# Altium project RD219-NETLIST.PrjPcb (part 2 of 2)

## Sheet 7.SchDoc
size 420 x 297 mm
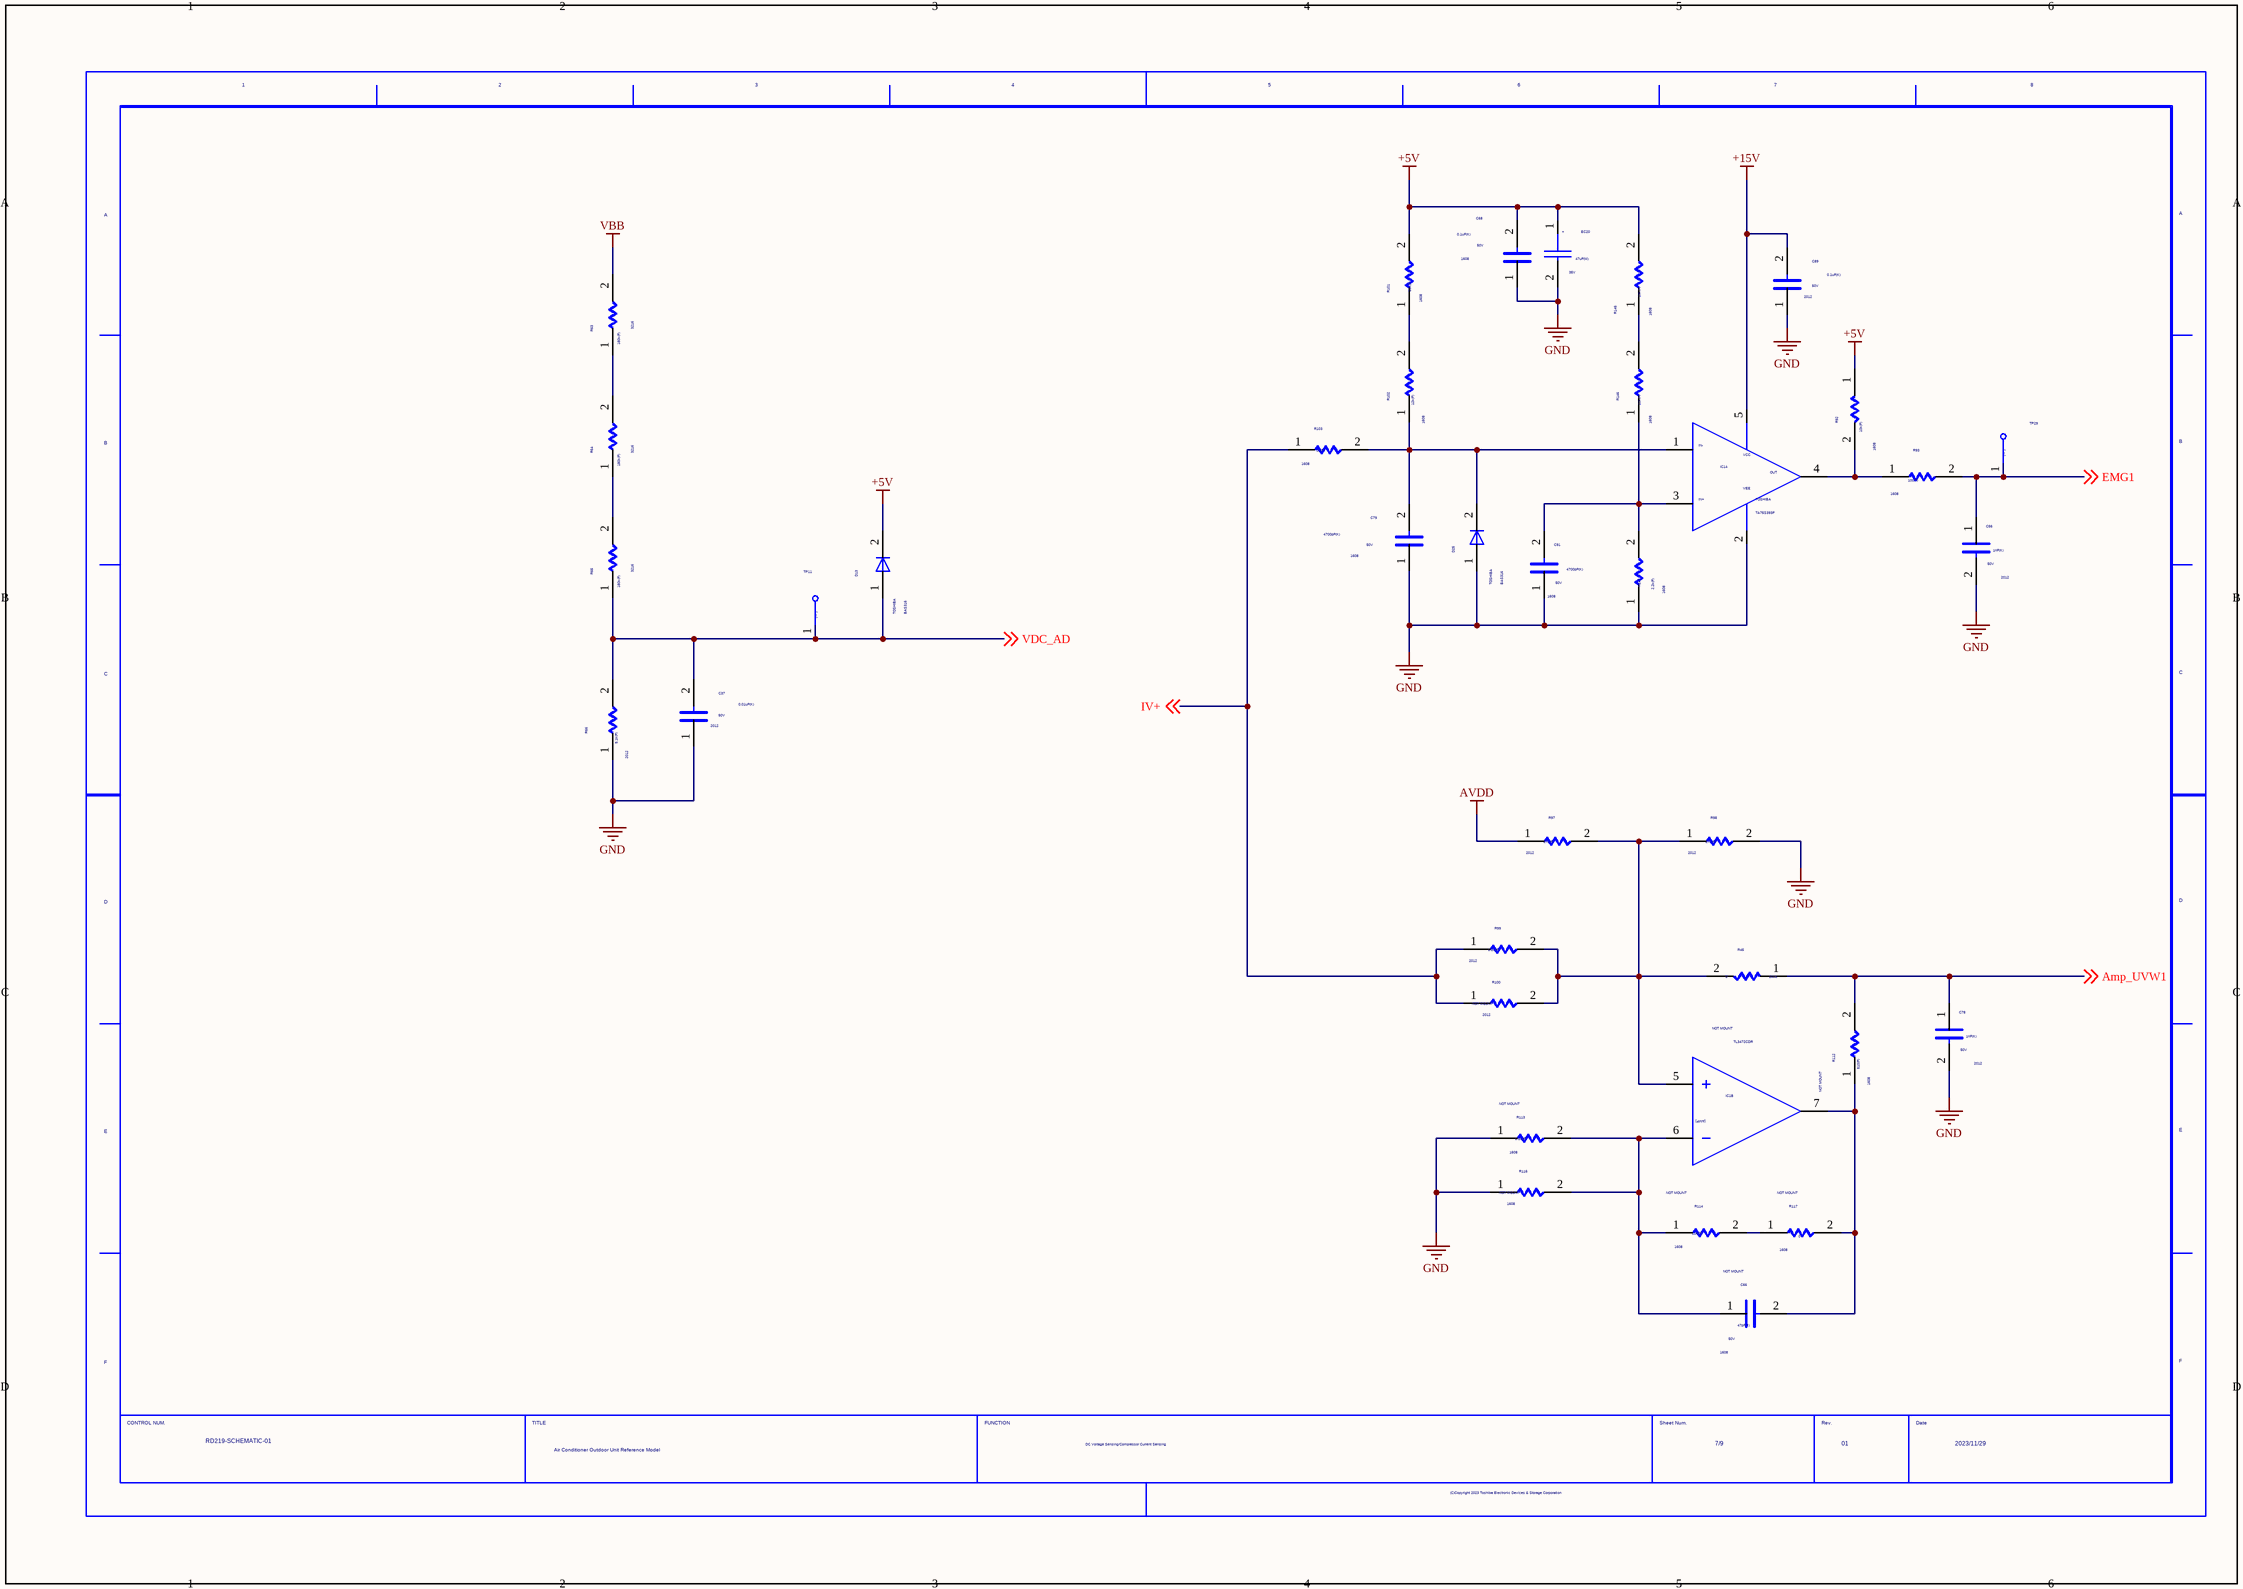
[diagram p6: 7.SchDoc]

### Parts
(Parts that share a designator on the sheet are numbered #1, #2 ... from top to bottom, then left to right.)
C37  SIZECODESMD: 2012  VAL2: 50V  VAL1: 0.01uF(K)  (hidden comment: C)
C56  VAL2: 50V  SIZECODESMD: 2012  VAL1: 1nF(K)  (hidden comment: C)
C66  NOTMOUNT: NOT MOUNT  VAL2: 50V  SIZECODESMD: 1608  VAL1: 47pF(J)  (hidden comment: C)
C68  VAL2: 50V  SIZECODESMD: 1608  VAL1: 0.1uF(K)  (hidden comment: C)
C78  VAL2: 50V  SIZECODESMD: 2012  VAL1: 1nF(K)  (hidden comment: C)
C79  VAL2: 50V  SIZECODESMD: 1608  VAL1: 4700pF(K)  (hidden comment: C)
C89  VAL2: 50V  SIZECODESMD: 2012  VAL1: 0.1uF(K)  (hidden comment: C)
C91  VAL2: 50V  SIZECODESMD: 1608  VAL1: 4700pF(K)  (hidden comment: C)
D13  USERCOMPTEXT3: TOSHIBA  VAL3: BAS316  (hidden comment: D_CUSTOM)
D25  USERCOMPTEXT3: TOSHIBA  VAL3: BAS316  (hidden comment: D_CUSTOM)
EC20  VAL2: 35V  VAL1: 47uF(M)  (hidden comment: EC)
IC1  NOTMOUNT: NOT MOUNT  VAL3: TL3472CDR  (hidden comment: AMP_1)  (part B of 2)
IC14  USERCOMPTEXT3: TOSHIBA  (hidden comment: TA75S393F)
R45  SIZECODESMD: 1608  VAL1: 0  (hidden comment: R)
R63  SIZECODESMD: 3216  VAL1: 180k(F)  (hidden comment: R)
R64  SIZECODESMD: 3216  VAL1: 180k(F)  (hidden comment: R)
R65  SIZECODESMD: 3216  VAL1: 180k(F)  (hidden comment: R)
R66  VAL1: 5.1k(F)  SIZECODESMD: 2012  (hidden comment: R)
R92  SIZECODESMD: 1608  VAL1: 10k(F)  (hidden comment: R)
R93  SIZECODESMD: 1608  VAL1: 100(F)  (hidden comment: R)
R97  SIZECODESMD: 2012  VAL1: 27k(F)  (hidden comment: R)
R98  SIZECODESMD: 2012  VAL1: 27k(F)  (hidden comment: R)
R99  SIZECODESMD: 2012  VAL1: 1.2k(F)  (hidden comment: R)
R100  SIZECODESMD: 2012  NOTMOUNT: NOT MOUNT  (hidden comment: R)
R101  SIZECODESMD: 1608  VAL1: 20k(F)  (hidden comment: R)
R102  SIZECODESMD: 1608  VAL1: 12k(F)  (hidden comment: R)
R103  SIZECODESMD: 1608  VAL1: 2k(F)  (hidden comment: R)
R112  NOTMOUNT: NOT MOUNT  SIZECODESMD: 1608  VAL1: 510(F)  (hidden comment: R)
R113  NOTMOUNT: NOT MOUNT  SIZECODESMD: 1608  VAL1: 1.1k(F)  (hidden comment: R)
R114  NOTMOUNT: NOT MOUNT  SIZECODESMD: 1608  VAL1: 12k(F)  (hidden comment: R)
R116  SIZECODESMD: 1608  NOTMOUNT: NOT MOUNT  (hidden comment: R)
R117  NOTMOUNT: NOT MOUNT  SIZECODESMD: 1608  VAL1: 0  (hidden comment: R)
R145  SIZECODESMD: 1608  VAL1: 10k(F)  (hidden comment: R)
R146  SIZECODESMD: 1608  VAL1: 12k(F)  (hidden comment: R)
R147  SIZECODESMD: 1608  VAL1: 2.2k(F)  (hidden comment: R)
TP11  TP  (value not drawn)
TP29  TP  (value not drawn)
U?#7  DATE: 2023/11/29  TITLE: Air Conditioner Outdoor Unit / Reference Model  FUNCTION: DC Voltage Sensing/Compressor Current Sensing  DRAWINGNUMBER: RD219-SCHEMATIC-01  SHEETNUMBER: 7/9  REVISION: 01  (hidden comment: WAKU_DEF100)

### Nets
+5V: C68.2 D13.2 EC20.1 R92.1 R101.2 R145.2
+15V: C89.2 IC14.5
AVDD: R97.1
GND: C37.1 C56.2 C68.1 C78.2 C79.1 C89.1 C91.1 D25.1 EC20.2 IC14.2 R66.1 R98.2 R113.1 R116.1 R147.1
VBB: R63.2
Amp_UVW1: C78.1 R45.1 R112.2 ; off-sheet Amp_UVW1
EMG1: C56.1 R93.2 TP29.1 ; off-sheet EMG1
IV+: R99.1 R100.1 R103.1 ; off-sheet IV+
NetC66_1: C66.1 IC1.6 R113.2 R114.1 R116.2
NetC66_2: C66.2 IC1.7 R112.1 R117.2
NetC79_2: C79.2 D25.2 IC14.1 R102.1 R103.2
NetC91_2: C91.2 IC14.3 R146.1 R147.2
NetIC1_5: IC1.5 R45.2 R97.2 R98.1 R99.2 R100.2
NetIC14_4: IC14.4 R92.2 R93.1
NetR63_1: R63.1 R64.2
NetR64_1: R64.1 R65.2
NetR101_1: R101.1 R102.2
NetR114_2: R114.2 R117.1
NetR145_1: R145.1 R146.2
VDC_AD: C37.2 D13.1 R65.1 R66.2 TP11.1 ; off-sheet VDC_AD

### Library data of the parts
C37 = C: OriginalSymbolOrigin: (2540,7620); VAL3: AC0805KRX7R9BB103
C56 C78 = C: OriginalSymbolOrigin: (2540,7620); COMP: AC0805KRX7R9BB102
C66 = C: OriginalSymbolOrigin: (2540,7620); COMP: AC0603JRNPO9BN470
C68 C89 = C: OriginalSymbolOrigin: (2540,7620); COMP: AC0603KRX7R9BB104
C79 C91 = C: OriginalSymbolOrigin: (2540,7620); COMP: AC0603KRX7R9BB472
D13 D25 = D_CUSTOM: SAVEAREA0: -1668,-97,14265,7829; SAVECOUNT: 4; TIME: 14:49:55; UPDATEUSER: w20165dm; UPDATETIME: 16:47:49; OriginalSymbolOrigin: (5080,5080)
EC20 = EC: SAVEAREA0: -1432,-1528,20311,14389; SAVECOUNT: 53; TIME: 15:02:55; UPDATEUSER: w20165dm; UPDATETIME: 16:35:05; OriginalSymbolOrigin: (2540,10160); VAL3: CS1V470M_CRE54
IC1 = AMP_1: SAVEAREA0: -6226,-235,36343,20943; TIME: 17:09:52; UPDATEUSER: w20165dm; SAVECOUNT: 1; OriginalSymbolOrigin: (5080,20320); CaptureCellPackProp: AMP_1B; FUNCN: IC1_2
IC14 = TA75S393F: SAVECOUNT: 22; SAVEAREA0: -11585,-294,41625,26178; TIME: 20:02:00; UPDATEUSER: w20165dm; UPDATETIME: 20:02:39; OriginalSymbolOrigin: (5080,22860)
R45 = R: OriginalSymbolOrigin: (5080,5080); COMP: AC0603FR_070RL; VAL3: AC0603FR-070RL; VAL2: 100mW
R63-R65 = R: OriginalSymbolOrigin: (5080,5080); VAL3: AC1206FR-07180KL; VAL2: 250mW; COMP: AC1206FR_07180KL
R66 = R: OriginalSymbolOrigin: (5080,5080); VAL3: AC0805FR-075K1L; VAL2: 125mW; COMP: AC0805FR_075K1L
R92 = R_Dup1: OriginalSymbolOrigin: (5080,5080); VAL2: 100mW; VAL3: AC0603FR_0710KL
R93 = R: OriginalSymbolOrigin: (5080,5080); COMP: AC0603FR_07100RL; VAL2: 100mW
R97 R98 = R: OriginalSymbolOrigin: (5080,5080); COMP: AC0805FR_0727KL; VAL2: 125mW
R99 = R: OriginalSymbolOrigin: (5080,5080); COMP: AC0805FR_071K2L; VAL2: 125mW
R100 = R: OriginalSymbolOrigin: (5080,5080); COMP: SMT_0805_R; VAL3: NC
R101 = R_Dup1: OriginalSymbolOrigin: (5080,5080); VAL3: AC0603FR_0720KL; VAL2: 100mW
R102 R146 = R_Dup1: OriginalSymbolOrigin: (5080,5080); VAL3: AC0603FR_0712KL; VAL2: 100mW
R103 = R: OriginalSymbolOrigin: (5080,5080); COMP: AC0603FR_072KL; VAL2: 100mW
R112 = R_Dup1: OriginalSymbolOrigin: (5080,5080); VAL2: 100mW; VAL3: AC0603FR_07510RL
R113 = R: OriginalSymbolOrigin: (5080,5080); COMP: AC0603FR_071K1L; VAL2: 100mW
R114 = R: OriginalSymbolOrigin: (5080,5080); COMP: AC0603FR_0712KL; VAL2: 100mW
R116 = R: OriginalSymbolOrigin: (5080,5080); COMP: SMT_0603_R
R117 = R: OriginalSymbolOrigin: (5080,5080); COMP: AC0603FR_070RL; VAL2: 100mW
R145 = R_Dup1: OriginalSymbolOrigin: (5080,5080); VAL3: AC0603FR_0710KL; VAL2: 100mW
R147 = R_Dup1: OriginalSymbolOrigin: (5080,5080); VAL3: AC0603FR_072K2L; VAL2: 100mW
TP11 = TP_Dup1: TIME: 16:12:21; UPDATEUSER: fukuda-y; UPDATETIME: 16:18:11; SAVECOUNT: 2; SAVEAREA0: -242,-92,12810,7836; OriginalSymbolOrigin: (0,7620); COMPCOMMENT: VDC_AD; VAL3: ZXD
TP29 = TP_Dup1: TIME: 16:12:21; UPDATEUSER: fukuda-y; UPDATETIME: 16:18:11; SAVECOUNT: 2; SAVEAREA0: -242,-92,12810,7836; OriginalSymbolOrigin: (0,7620); COMPCOMMENT: EMG1; VAL3: ZXD
U?#7 = WAKU_DEF100: PLOTTIME: HH:MM; SAVEAREA0: -45080,-4508,463680,304612; TIME: 18:03:30; UPDATEUSER: sptcae13; UPDATETIME: 08:19:31; SAVECOUNT: 8; OriginalSymbolOrigin: (10160,284480)

## Sheet 8.SchDoc
size 420 x 297 mm
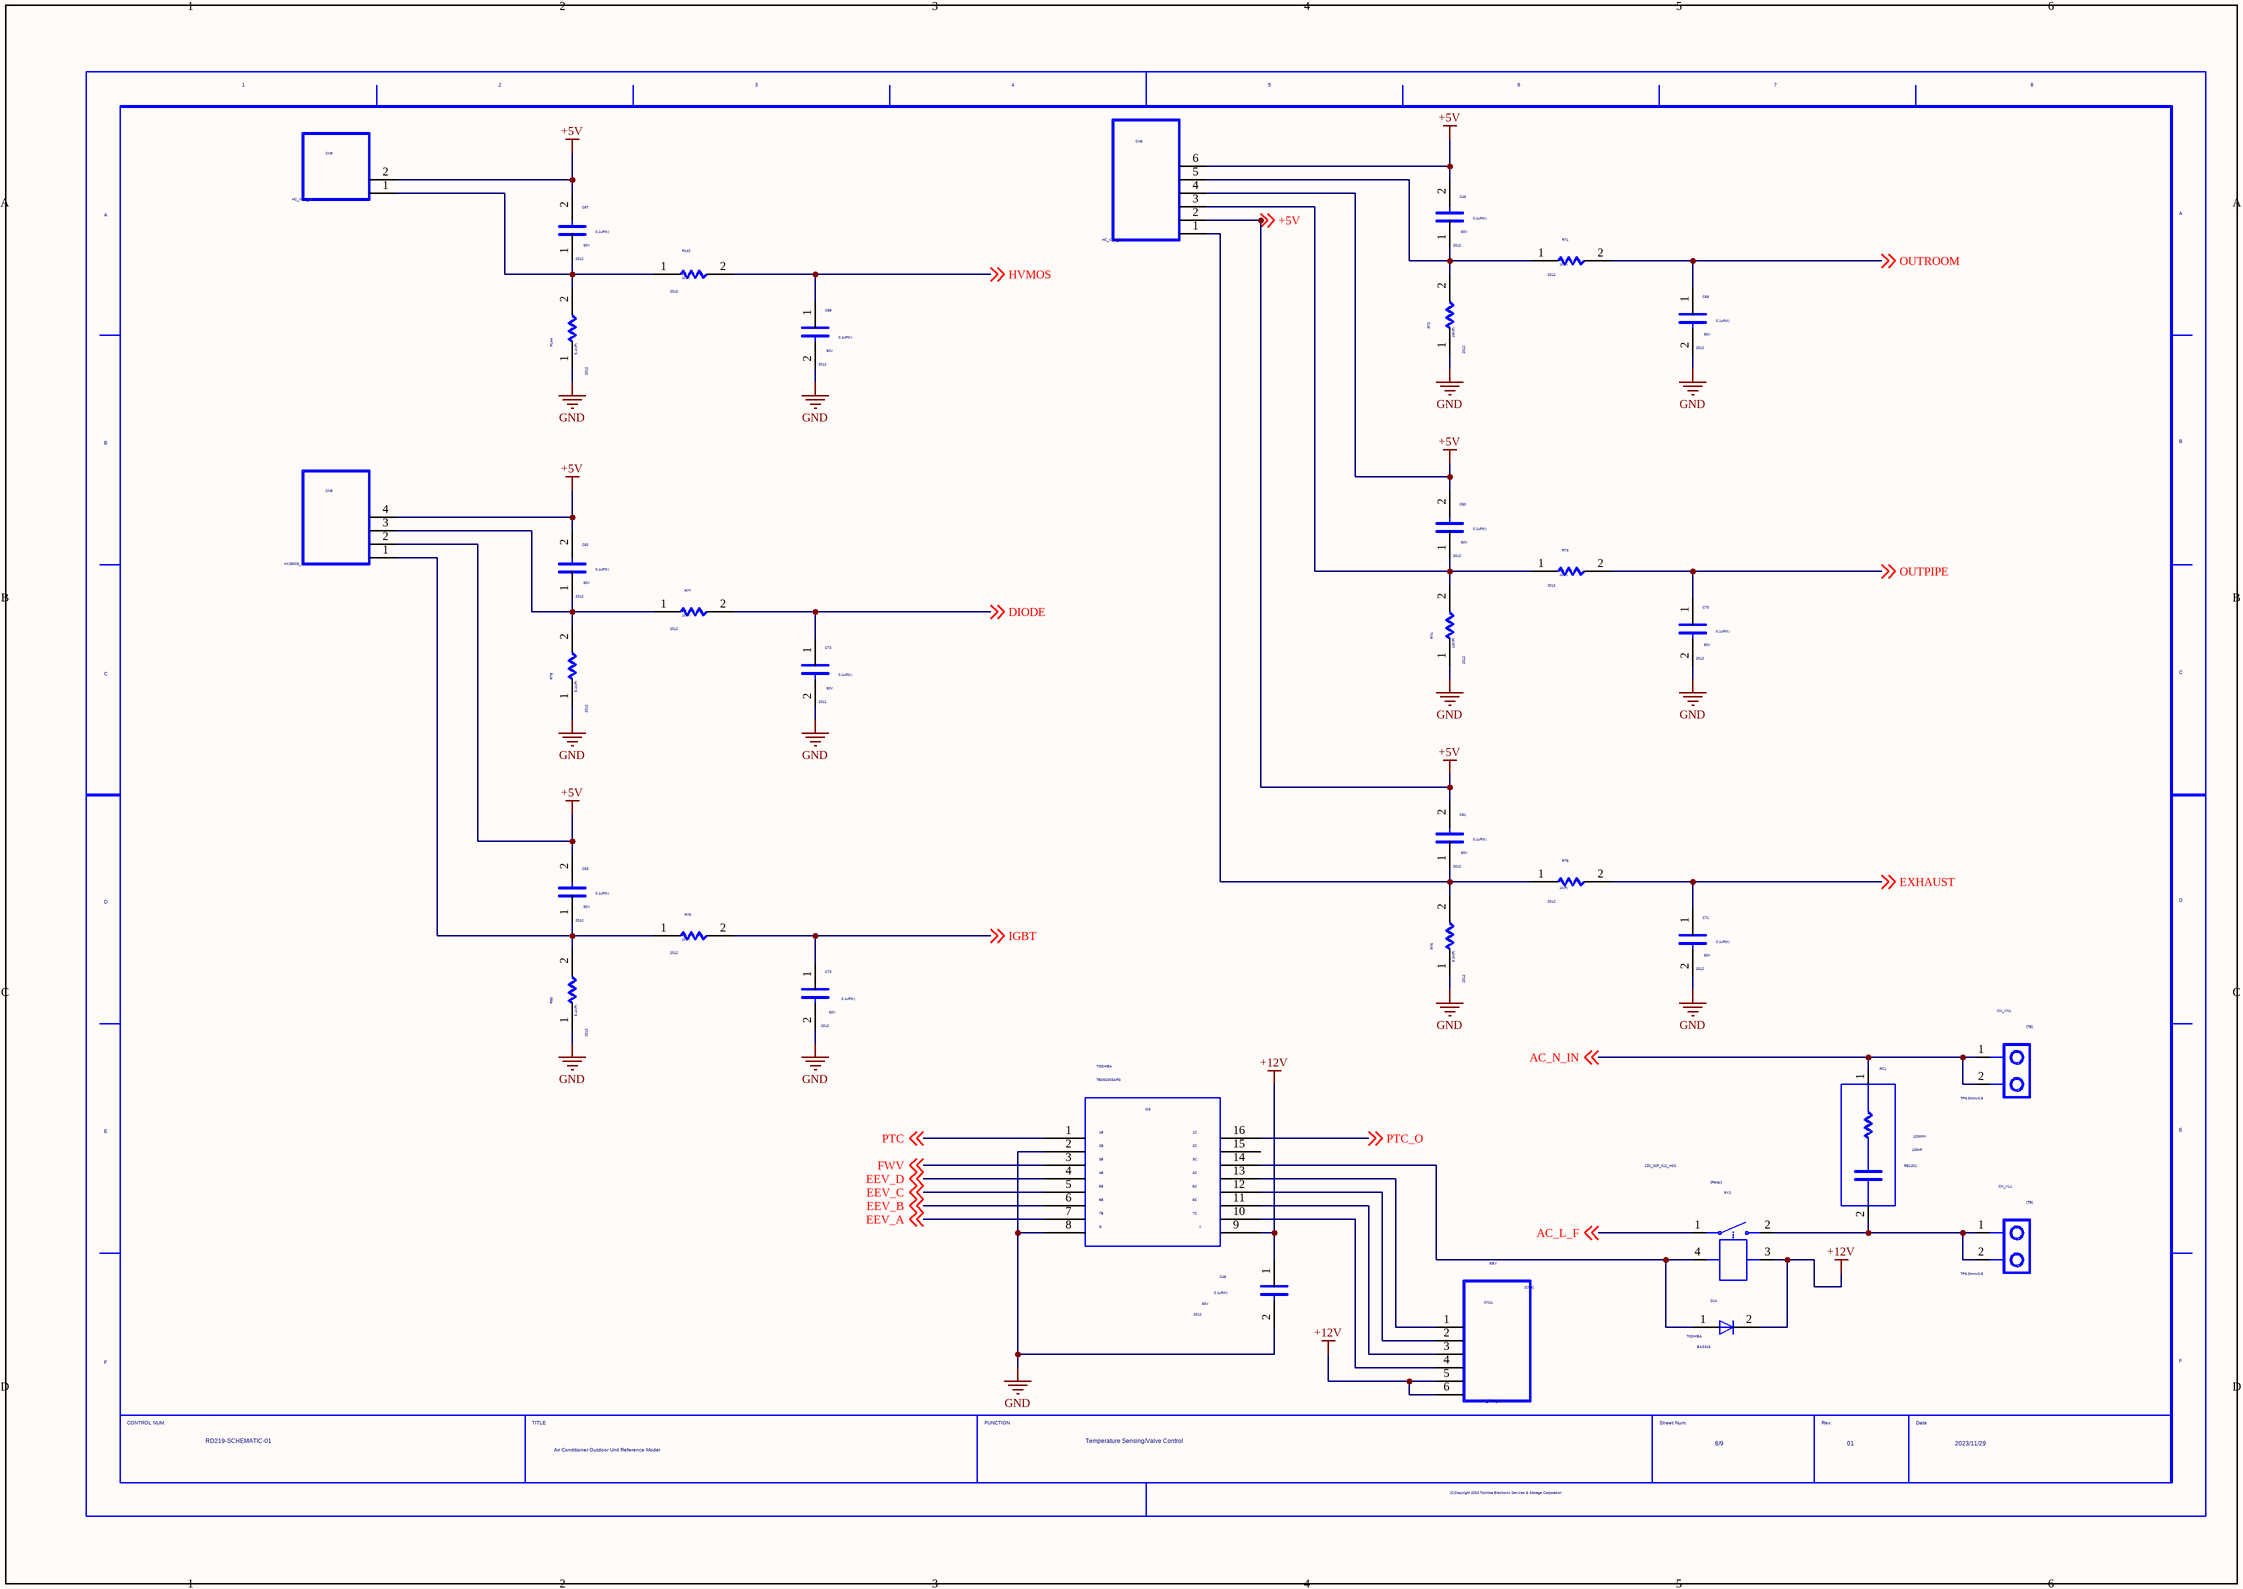
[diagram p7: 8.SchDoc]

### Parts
(Parts that share a designator on the sheet are numbered #1, #2 ... from top to bottom, then left to right.)
C48  SIZECODESMD: 2012  VAL2: 50V  VAL1: 0.1uF(K)  (hidden comment: C)
C49  SIZECODESMD: 2012  VAL2: 50V  VAL1: 0.1uF(K)  (hidden comment: C)
C50  SIZECODESMD: 2012  VAL2: 50V  VAL1: 0.1uF(K)  (hidden comment: C)
C51  SIZECODESMD: 2012  VAL2: 50V  VAL1: 0.1uF(K)  (hidden comment: C)
C52  SIZECODESMD: 2012  VAL2: 50V  VAL1: 0.1uF(K)  (hidden comment: C)
C53  SIZECODESMD: 2012  VAL2: 50V  VAL1: 0.1uF(K)  (hidden comment: C)
C69  SIZECODESMD: 2012  VAL2: 50V  VAL1: 0.1uF(K)  (hidden comment: C)
C70  SIZECODESMD: 2012  VAL2: 50V  VAL1: 0.1uF(K)  (hidden comment: C)
C71  SIZECODESMD: 2012  VAL2: 50V  VAL1: 0.1uF(K)  (hidden comment: C)
C72  SIZECODESMD: 2012  VAL2: 50V  VAL1: 0.1uF(K)  (hidden comment: C)
C73  SIZECODESMD: 2012  VAL2: 50V  VAL1: 0.1uF(K)  (hidden comment: C)
C87  SIZECODESMD: 2012  VAL2: 50V  VAL1: 0.1uF(K)  (hidden comment: C)
C88  SIZECODESMD: 2012  VAL2: 50V  VAL1: 0.1uF(K)  (hidden comment: C)
CN5  VAL3: HC_XHB_6A  (hidden comment: CN6Y)
CN8  VAL3: HX25003_4A  (hidden comment: CN4Y)
CN9  VAL3: HC_XHB_2A  (hidden comment: CN2Y)
CN11  VAL3: HC_XHB_6A  COMPCOMMENT: EEV  (hidden comment: CN6)
CN_VL1  COMPCOMMENT: TP6.3mmx0.8  (hidden comment: TB2A)
CN_VN1  COMPCOMMENT: TP6.3mmx0.8  (hidden comment: TB2A)
D14  USERCOMPTEXT3: TOSHIBA  VAL3: BAS316  (hidden comment: D_CUSTOM)
IC9  USERCOMPTEXT3: TOSHIBA  VAL1: TBD62003AFG  (hidden comment: TBD62003)
R71  SIZECODESMD: 2012  VAL1: 1k(F)  (hidden comment: R)
R72  SIZECODESMD: 2012  VAL1: 10k(F)  (hidden comment: R)
R73  SIZECODESMD: 2012  VAL1: 1k(F)  (hidden comment: R)
R74  SIZECODESMD: 2012  VAL1: 10k(F)  (hidden comment: R)
R75  SIZECODESMD: 2012  VAL1: 1k(F)  (hidden comment: R)
R76  SIZECODESMD: 2012  VAL1: 5.1k(F)  (hidden comment: R)
R77  SIZECODESMD: 2012  VAL1: 1k(F)  (hidden comment: R)
R78  SIZECODESMD: 2012  VAL1: 5.1k(F)  (hidden comment: R)
R79  SIZECODESMD: 2012  VAL1: 1k(F)  (hidden comment: R)
R80  SIZECODESMD: 2012  VAL1: 5.1k(F)  (hidden comment: R)
R142  SIZECODESMD: 2012  VAL1: 1k(F)  (hidden comment: R)
R144  SIZECODESMD: 2012  VAL1: 5.1k(F)  (hidden comment: R)
RC1  VAL2: 120ohm  VAL1: 100nF  VAL3: RE1201  (hidden comment: RC)
RY2  VAL1: JZC_32F_012_HS3  (hidden comment: SFK-112)
U?#8  DATE: 2023/11/29  TITLE: Air Conditioner Outdoor Unit / Reference Model  DRAWINGNUMBER: RD219-SCHEMATIC-01  SHEETNUMBER: 8/9  FUNCTION: Temperature Sensing/Valve Control  REVISION: 01  (hidden comment: WAKU_DEF100)

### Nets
+5V: C49.2 C50.2 C51.2 C52.2 C53.2 C87.2 CN5.2 CN5.4 CN5.6 CN8.2 CN8.4 CN9.2 ; off-sheet +5V
+12V: C48.1 CN11.5 CN11.6 D14.2 IC9.9 RY2.3
GND: C48.2 C69.2 C70.2 C71.2 C72.2 C73.2 C88.2 IC9.2 IC9.8 R72.1 R74.1 R76.1 R78.1 R80.1 R144.1
AC_L_F: RY2.1 ; off-sheet AC_L_F
AC_N_IN: CN_VN1.1 CN_VN1.2 RC1.1 ; off-sheet AC_N_IN
DIODE: C72.1 R77.2 ; off-sheet DIODE
EEV_A: IC9.7 ; off-sheet EEV_A
EEV_B: IC9.6 ; off-sheet EEV_B
EEV_C: IC9.5 ; off-sheet EEV_C
EEV_D: IC9.4 ; off-sheet EEV_D
EXHAUST: C71.1 R75.2 ; off-sheet EXHAUST
FWV: IC9.3 ; off-sheet FWV
HVMOS: C88.1 R142.2 ; off-sheet HVMOS
IGBT: C73.1 R79.2 ; off-sheet IGBT
NetC49_1: C49.1 CN5.5 R71.1 R72.2
NetC50_1: C50.1 CN5.3 R73.1 R74.2
NetC51_1: C51.1 CN5.1 R75.1 R76.2
NetC52_1: C52.1 CN8.3 R77.1 R78.2
NetC53_1: C53.1 CN8.1 R79.1 R80.2
NetC87_1: C87.1 CN9.1 R142.1 R144.2
NetCN11_1: CN11.1 IC9.13
NetCN11_2: CN11.2 IC9.12
NetCN11_3: CN11.3 IC9.11
NetCN11_4: CN11.4 IC9.10
NetCN-VL1_1: CN_VL1.1 CN_VL1.2 RC1.2 RY2.2
NetD14_1: D14.1 IC9.14 RY2.4
OUTPIPE: C70.1 R73.2 ; off-sheet OUTPIPE
OUTROOM: C69.1 R71.2 ; off-sheet OUTROOM
PTC: IC9.1 ; off-sheet PTC
PTC_O: IC9.16 ; off-sheet PTC_O

Not connected (* = marked no-connect by the designer): IC9 15

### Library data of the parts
C48 = C_Dup1: OriginalSymbolOrigin: (2540,7620); VAL3: AC0805KRX7R9BB104
C49-C53 C69-C73 C87 C88 = C: OriginalSymbolOrigin: (2540,7620); VAL3: AC0805KRX7R9BB104
CN5 = CN6Y: SAVEAREA0: -8909,-546,28423,26783; TIME: 09:54:13; UPDATEUSER: w20165dm; SAVECOUNT: 1; OriginalSymbolOrigin: (2540,25400)
CN8 = CN4Y: SAVEAREA0: -5115,-437,24748,21425; TIME: 09:53:19; UPDATEUSER: w20165dm; SAVECOUNT: 1; OriginalSymbolOrigin: (2540,20320)
CN9 = CN2Y: SAVEAREA0: -6573,-310,26384,16086; TIME: 09:52:32; UPDATEUSER: w20165dm; SAVECOUNT: 1; OriginalSymbolOrigin: (2540,15240); COMPCOMMENT: TEMP3
CN11 = CN6: OriginalSymbolOrigin: (2540,25400)
CN_VL1 CN_VN1 = TB2A: SAVEAREA0: -6249,-369,19007,18120; TIME: 11:16:32; UPDATEUSER: w20165dm; SAVECOUNT: 1; OriginalSymbolOrigin: (2540,12700); VAL3: DJ6110-6.3x0.8; COMP: TP
D14 = D_CUSTOM: as D13 on sheet 7
IC9 = TBD62003: SAVECOUNT: 34; SAVEAREA0: -8546,-383,48557,34032; TIME: 11:13:04; UPDATEUSER: w20165dm; UPDATETIME: 19:36:15; OriginalSymbolOrigin: (7620,30480)
R71 R75 = R: OriginalSymbolOrigin: (5080,5080); VAL3: AC0805FR-071KL; VAL2: 125mW; COMP: AC0805FR_071KL
R72 R74 = R: OriginalSymbolOrigin: (5080,5080); VAL3: AC0805FR-0710KL; VAL2: 125mW; COMP: AC08005FR_0710KL
R73 R77 R79 = R: OriginalSymbolOrigin: (5080,5080); VAL2: 125mW; VAL3: AC0805FR-071KL; COMP: AC0805FR_071KL
R76 = R: OriginalSymbolOrigin: (5080,5080); COMP: AC0805FR_075K1L; VAL3: AC0805FR-075K1L; VAL2: 125mW
R78 = R: OriginalSymbolOrigin: (5080,5080); VAL2: 125mW; VAL3: AC0805FR-075K1L; COMP: AC0805FR_075K1L
R80 = R: as R66 on sheet 7
R142 = R: OriginalSymbolOrigin: (5080,5080); VAL3: AC0805FR_071KL; VAL2: 125mW
R144 = R: OriginalSymbolOrigin: (5080,5080); VAL3: AC0805FR_075K1L; VAL2: 125mW
RC1 = RC: SAVEAREA0: -17024,-284,34362,28697; TIME: 17:42:57; UPDATEUSER: w20165dm; UPDATETIME: 17:46:02; SAVECOUNT: 2; OriginalSymbolOrigin: (2540,25400)
RY2 = SFK-112: SAVEAREA0: -13231,-231,28521,20540; TIME: 14:06:16; UPDATEUSER: w20165dm; UPDATETIME: 17:57:42; SAVECOUNT: 24; OriginalSymbolOrigin: (2540,12700)
U?#8 = WAKU_DEF100: PLOTTIME: HH:MM; SAVEAREA0: -45080,-4508,463680,304612; TIME: 11:16:27; UPDATEUSER: sptcae13; UPDATETIME: 08:19:31; SAVECOUNT: 8; OriginalSymbolOrigin: (10160,284480)

## Sheet 9.SchDoc
size 420 x 297 mm
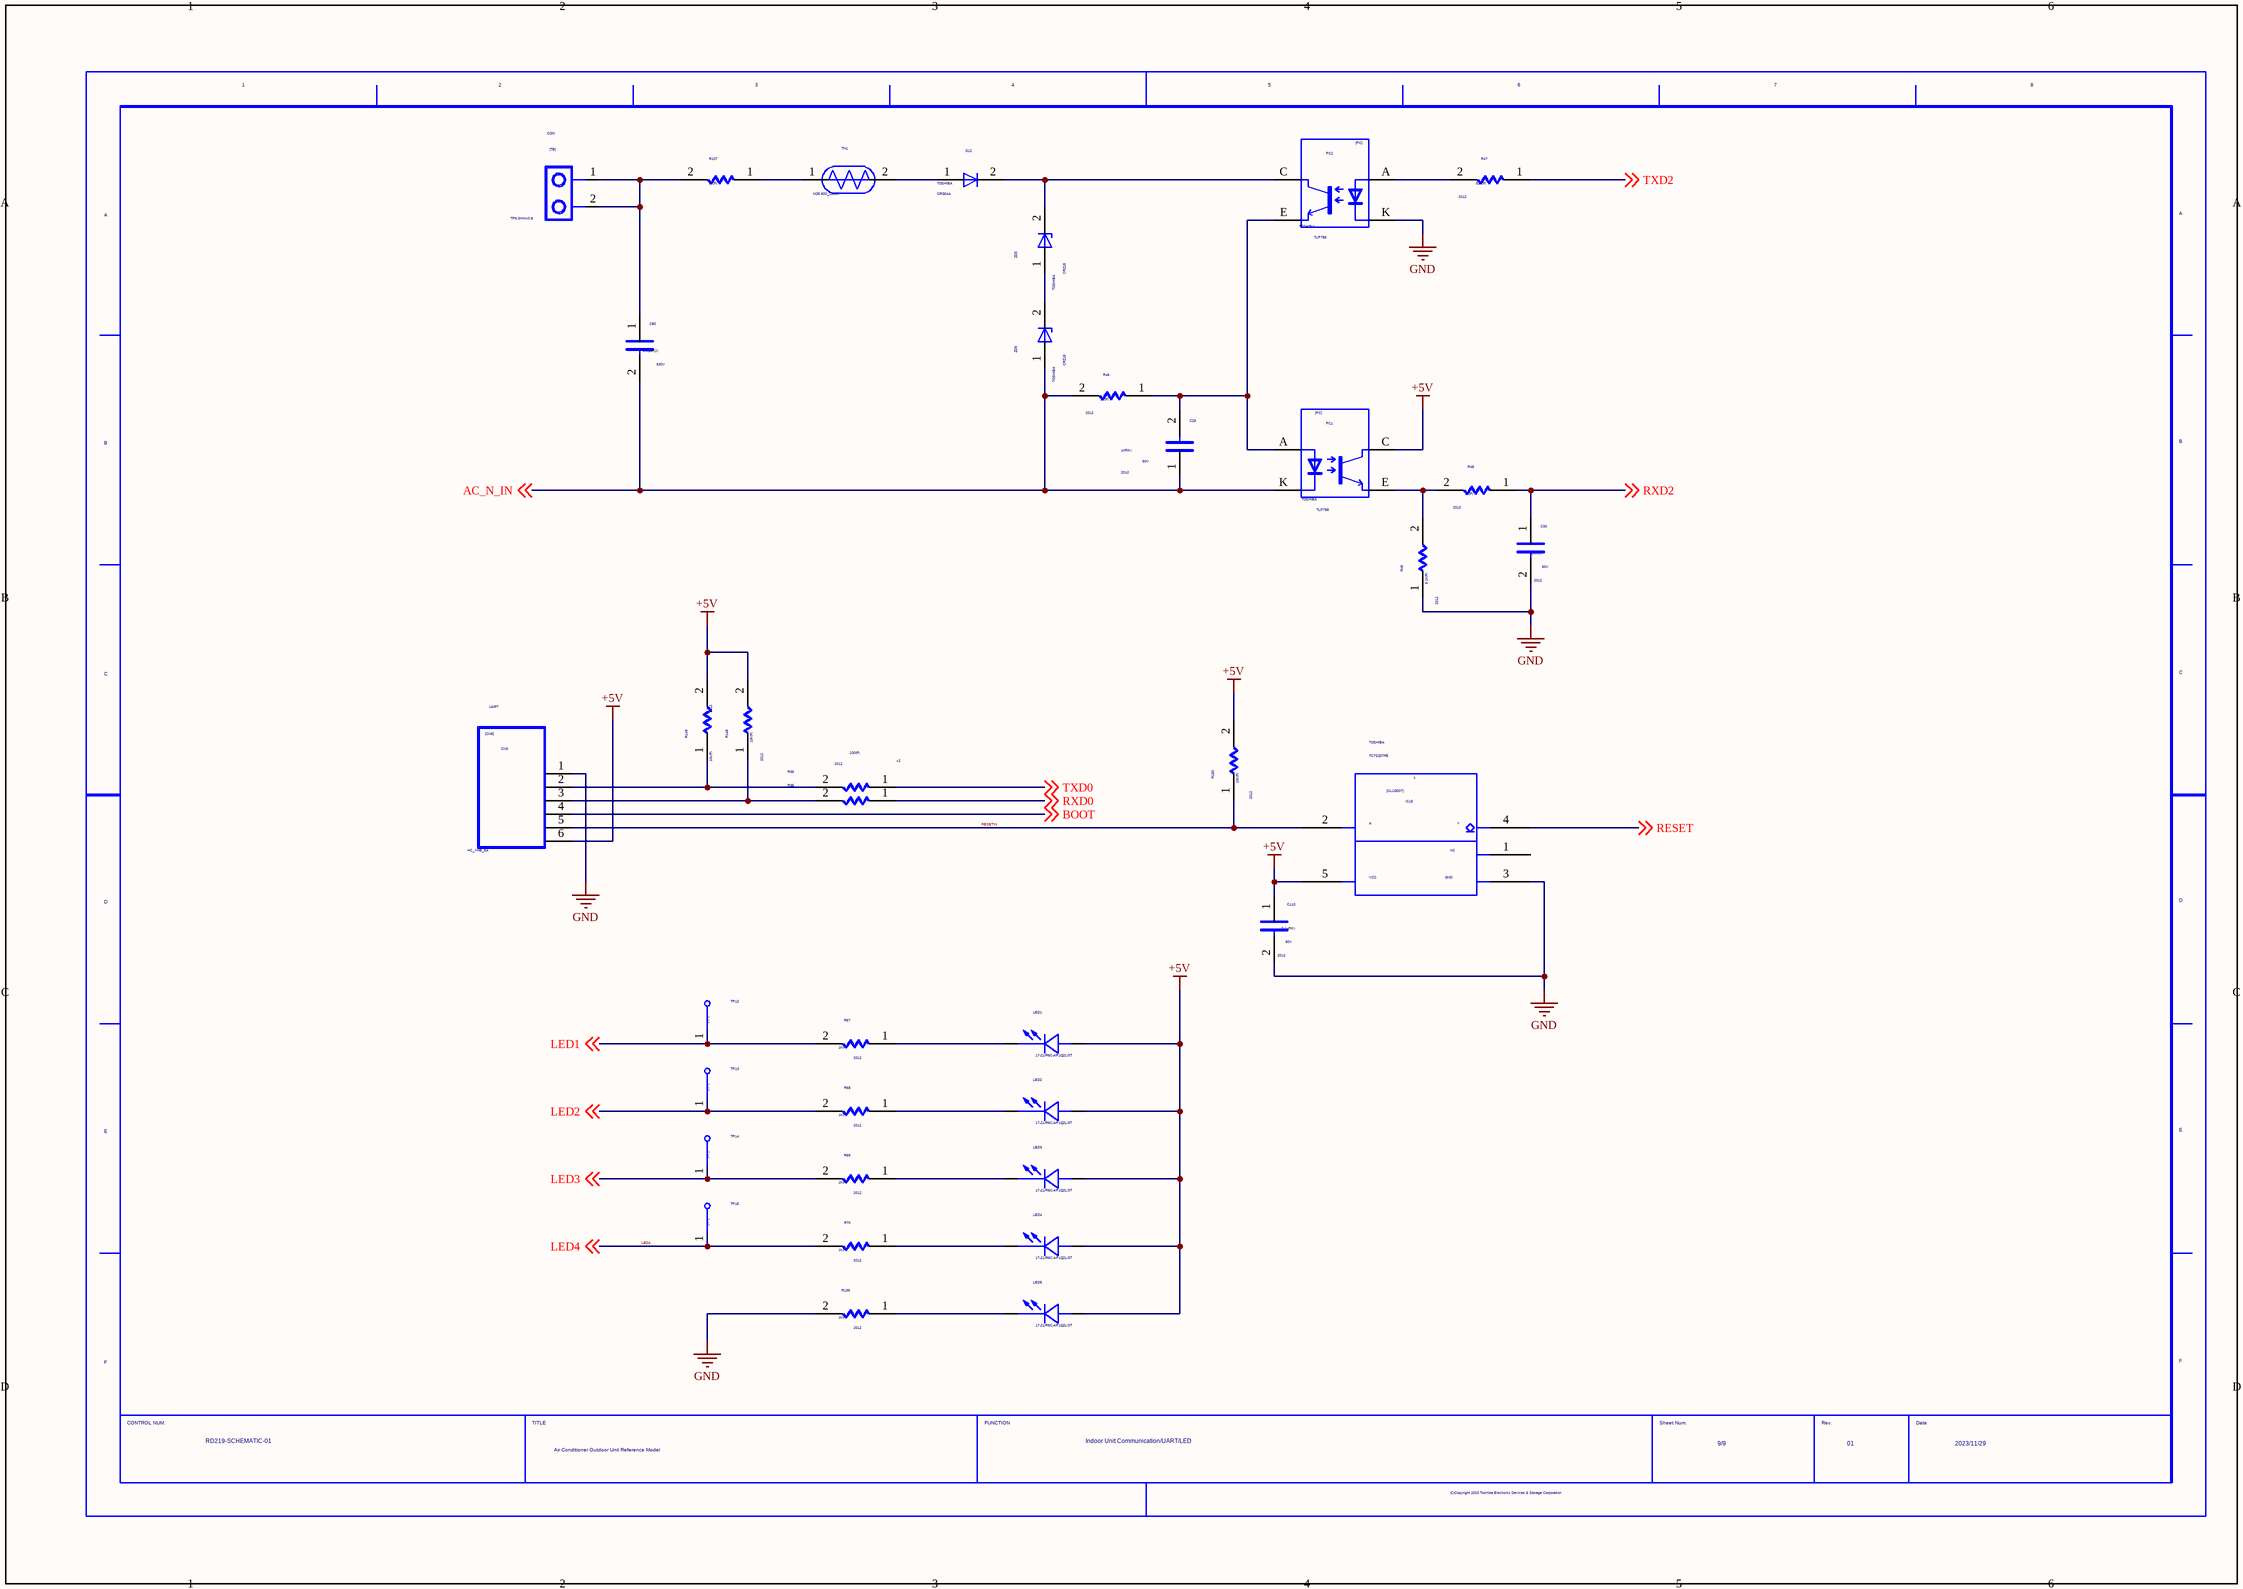
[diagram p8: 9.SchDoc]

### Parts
(Parts that share a designator on the sheet are numbered #1, #2 ... from top to bottom, then left to right.)
C29  SIZECODESMD: 2012  VAL2: 50V  VAL1: 1nF(K)  (hidden comment: C)
C30  SIZECODESMD: 2012  VAL2: 50V  VAL1: 1nF(K)  (hidden comment: C)
C80  VAL1: 0.01uF(J)  VAL2: 630V  (hidden comment: C)
C110  SIZECODESMD: 2012  VAL2: 50V  VAL1: 0.1uF(K)  (hidden comment: C)
CN3  VAL3: HC_XHB_6A  COMPCOMMENT: UART  (hidden comment: CN6)
COM  COMPCOMMENT: TP6.3mmx0.8  (hidden comment: TB2A)
D12  USERCOMPTEXT3: TOSHIBA  VAL3: CRG04A  (hidden comment: D_CUSTOM)
IC15  USERCOMPTEXT3: TOSHIBA  VAL1: TC7SZ07FE  (hidden comment: CL1G007)
LED1  VAL3: 17-21/R6C-AP1Q2L/3T  (hidden comment: LED)
LED2  VAL3: 17-21/R6C-AP1Q2L/3T  (hidden comment: LED)
LED3  VAL3: 17-21/R6C-AP1Q2L/3T  (hidden comment: LED)
LED4  VAL3: 17-21/R6C-AP1Q2L/3T  (hidden comment: LED)
LED5  VAL3: 17-21/R6C-AP1Q2L/3T  (hidden comment: LED)
PC1  USERCOMPTEXT3: TOSHIBA  (hidden comment: TLP785)
PC2  USERCOMPTEXT3: TOSHIBA  (hidden comment: TLP785)
R35  R  (value not drawn)
R36  SIZECODESMD: 2012  VAL1: 100(F)  (hidden comment: R)
R46  SIZECODESMD: 2012  VAL1: 2k(F)  (hidden comment: R)
R47  SIZECODESMD: 2012  VAL1: 510(F)  (hidden comment: R)
R48  SIZECODESMD: 2012  VAL1: 1k(F)  (hidden comment: R)
R49  SIZECODESMD: 2012  VAL1: 5.1k(F)  (hidden comment: R)
R67  SIZECODESMD: 2012  VAL1: 1k(F)  (hidden comment: R)
R68  SIZECODESMD: 2012  VAL1: 1k(F)  (hidden comment: R)
R69  SIZECODESMD: 2012  VAL1: 1k(F)  (hidden comment: R)
R70  SIZECODESMD: 2012  VAL1: 1k(F)  (hidden comment: R)
R107  VAL1: 2k(F)  (hidden comment: R)
R136  SIZECODESMD: 2012  VAL1: 1k(F)  (hidden comment: R)
R148  SIZECODESMD: 2012  VAL1: 10k(F)  (hidden comment: R)
R149  SIZECODESMD: 2012  VAL1: 10k(F)  (hidden comment: R)
R150  SIZECODESMD: 2012  VAL1: 10k(F)  (hidden comment: R)
TH1  VAL1: MZ6 800_1200R  (hidden comment: PTC)
TP12  TP  (value not drawn)
TP13  TP  (value not drawn)
TP14  TP  (value not drawn)
TP15  TP  (value not drawn)
U?#9  DATE: 2023/11/29  TITLE: Air Conditioner Outdoor Unit / Reference Model  SHEETNUMBER: 9/9  DRAWINGNUMBER: RD219-SCHEMATIC-01  FUNCTION: Indoor Unit Communication/UART/LED  REVISION: 01  (hidden comment: WAKU_DEF100)
ZD3  USERCOMPTEXT3: TOSHIBA  VAL1: CRZ15  (hidden comment: ZD)
ZD9  USERCOMPTEXT3: TOSHIBA  VAL1: CRZ15  (hidden comment: ZD)

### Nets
+5V: C110.1 CN3.6 IC15.5 LED1.1 LED2.1 LED3.1 LED4.1 LED5.1 PC1.C R148.2 R149.2 R150.2
GND: C30.2 C110.2 CN3.1 IC15.3 PC2.K R49.1 R136.2
AC_N_IN: C29.1 C80.2 PC1.K R46.2 ZD9.1(A) ; off-sheet AC_N_IN
BOOT: CN3.4 ; off-sheet BOOT
LED1: R67.2 TP12.1 ; off-sheet LED1
LED2: R68.2 TP13.1 ; off-sheet LED2
LED3: R69.2 TP14.1 ; off-sheet LED3
LED4: R70.2 TP15.1 ; off-sheet LED4
NetC29_2: C29.2 PC1.A PC2.E R46.1
NetC80_1: C80.1 COM.1 COM.2 R107.2
NetCN3_2: CN3.2 R36.2 R149.1
NetCN3_3: CN3.3 R35.2 R148.1
NetD12_1: D12.1 TH1.2
NetD12_2: D12.2 PC2.C ZD3.2(C)
NetLED1_2: LED1.2 R67.1
NetLED2_2: LED2.2 R68.1
NetLED3_2: LED3.2 R69.1
NetLED4_2: LED4.2 R70.1
NetLED5_2: LED5.2 R136.1
NetPC1_E: PC1.E R48.2 R49.2
NetPC2_A: PC2.A R47.2
NetR107_1: R107.1 TH1.1
NetZD3_1: ZD3.1(A) ZD9.2(C)
RESET: IC15.4 ; off-sheet RESET
RESETIN: CN3.5 IC15.2 R150.1
RXD0: R35.1 ; off-sheet RXD0
RXD2: C30.1 R48.1 ; off-sheet RXD2
TXD0: R36.1 ; off-sheet TXD0
TXD2: R47.1 ; off-sheet TXD2

Not connected (* = marked no-connect by the designer): IC15 1

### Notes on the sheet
- x2

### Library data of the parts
C29 C30 = C: OriginalSymbolOrigin: (2540,7620); VAL3: AC0805KRX7R9BB102
C80 = C: OriginalSymbolOrigin: (2540,7620); VAL3: CBB22_103J630V
C110 = C: as C49-C53 on sheet 8
CN3 = CN6: OriginalSymbolOrigin: (2540,25400)
COM = TB2A: as CN_VL1 on sheet 8
D12 = D_CUSTOM: as D13 on sheet 7
IC15 = CL1G007: TIME: 15:16:30; UPDATEUSER: 19990028; UPDATETIME: 09:49:48; SAVECOUNT: 10; SAVEAREA0: -1829,-329,45053,28196; OriginalSymbolOrigin: (7620,25400)
LED1-LED5 = LED: COMP: 17_21_R6C_AP1Q2L_3T; TIME: 09:29:00; UPDATEUSER: sptcae13; UPDATETIME: 17:03:31; SAVECOUNT: 2; SAVEAREA0: -3132,-7866,12954,3909; OriginalSymbolOrigin: (0,0)
PC1 PC2 = TLP785: SAVEAREA0: -3804,-437,26060,21425; TIME: 09:38:30; UPDATEUSER: w20165dm; SAVECOUNT: 1; OriginalSymbolOrigin: (5080,17780)
R35 = R: OriginalSymbolOrigin: (5080,5080); SIZECODESMD: 2012; VAL3: AC0805FR-07100RL; VAL2: 125mW; VAL1: 100(F); COMP: AC0805FR_07100RL
R36 = R: OriginalSymbolOrigin: (5080,5080); VAL2: 125mW; VAL3: AC0805FR-07100RL; COMP: AC0805FR_07100RL
R46 = R: OriginalSymbolOrigin: (5080,5080); VAL2: 125mW; VAL3: AC0805FR-072KL; COMP: AC0805FR_072KL
R47 = R: OriginalSymbolOrigin: (5080,5080); VAL2: 125mW; VAL3: AC0805FR-07510RL; COMP: AC0805FR_07510RL
R48 = R: as R73 on sheet 8
R49 = R: as R66 on sheet 7
R67-R70 = R: as R71 on sheet 8
R107 = R: OriginalSymbolOrigin: (5080,5080); VAL3: MFR100FTE52_2K; VAL2: 1W
R136 = R: as R142 on sheet 8
R148-R150 = R: OriginalSymbolOrigin: (5080,5080); VAL2: 125mW; VAL3: AC0805FR_0710KL; COMP: AC08005FR_0710KL
TH1 = PTC: TIME: 17:09:47; UPDATEUSER: w20165dm; UPDATETIME: 17:16:29; SAVECOUNT: 2; SAVEAREA0: -4525,-147,22079,13088; OriginalSymbolOrigin: (5080,7620); COMP: MZ6_800_1200R
TP12 = TP_Dup1: TIME: 16:12:21; UPDATEUSER: fukuda-y; UPDATETIME: 16:18:11; SAVECOUNT: 2; SAVEAREA0: -242,-92,12810,7836; OriginalSymbolOrigin: (0,7620); COMPCOMMENT: LED1; VAL3: ZXD
TP13 = TP_Dup1: TIME: 16:12:21; UPDATEUSER: fukuda-y; UPDATETIME: 16:18:11; SAVECOUNT: 2; SAVEAREA0: -242,-92,12810,7836; OriginalSymbolOrigin: (0,7620); COMPCOMMENT: LED2; VAL3: ZXD
TP14 = TP_Dup1: TIME: 16:12:21; UPDATEUSER: fukuda-y; UPDATETIME: 16:18:11; SAVECOUNT: 2; SAVEAREA0: -242,-92,12810,7836; OriginalSymbolOrigin: (0,7620); COMPCOMMENT: LED3; VAL3: ZXD
TP15 = TP_Dup1: TIME: 16:12:21; UPDATEUSER: fukuda-y; UPDATETIME: 16:18:11; SAVECOUNT: 2; SAVEAREA0: -242,-92,12810,7836; OriginalSymbolOrigin: (0,7620); COMPCOMMENT: LED4; VAL3: ZXD
U?#9 = WAKU_DEF100: PLOTTIME: HH:MM; SAVEAREA0: -45080,-4508,463680,304612; TIME: 12:03:07; UPDATEUSER: sptcae13; UPDATETIME: 08:19:31; SAVECOUNT: 8; OriginalSymbolOrigin: (10160,284480)
ZD3 ZD9 = ZD: SAVEAREA0: -4071,-115,16804,10270; TIME: 09:43:08; UPDATEUSER: w20165dm; UPDATETIME: 16:32:57; SAVECOUNT: 6; OriginalSymbolOrigin: (5080,5080)

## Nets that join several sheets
+5V: 2 (C23.1 EC5.1 IC3.3 TP3.1), 3 (9 pins), 4 (5 pins), 6 (C16.2 IC6.8 R13.2 R18.2), 7 (6 pins), 8 (12 pins), 9 (12 pins)
+12V: 1 (D1.2 RY1.3), 2 (5 pins), 8 (6 pins)
+15V: 1 (C21.2 EC15.1 IC7.6), 2 (7 pins), 4 (C31.1 EC7.1 IC8.5), 5 (12 pins), 6 (C15.2 EC17.1 IC5.8), 7 (C89.2 IC14.5)
AVDD: 3 (7 pins), 4 (C86.1 R55.1), 6 (R7.1 R31.1), 7 (R97.1)
GND: 1 (15 pins), 2 (21 pins), 3 (23 pins), 4 (25 pins), 5 (11 pins), 6 (19 pins), 7 (15 pins), 8 (15 pins), 9 (7 pins)
VBB: 1 (C10.2 D2.2 EC1.1 EC2.1), 2 (BYQ.2 D3.2), 4 (C90.2 IC8.23 IC8.24), 5 (7 pins), 7 (R63.2)
AC_L: 1 (BG1.3 PTC.2 RY1.1), 6 (R23.1)
AC_L_F: 1 (6 pins), 8 (RY2.1)
AC_N: 1 (5 pins), 6 (R26.1)
AC_N_IN: 1 (5 pins), 8 (CN_VN1.1 CN_VN1.2 RC1.1), 9 (5 pins)
Amp_UVW0: 3 (IC11.13), 4 (C36.1 R83.1 R109.2)
Amp_UVW1: 3 (IC11.15), 7 (C78.1 R45.1 R112.2)
BOOT: 3 (IC11.44 R108.2), 9 (CN3.4)
DIODE: 3 (IC11.18), 8 (C72.1 R77.2)
EEV_A: 3 (IC11.4), 8 (IC9.7)
EEV_B: 3 (IC11.5), 8 (IC9.6)
EEV_C: 3 (IC11.11), 8 (IC9.5)
EEV_D: 3 (IC11.12), 8 (IC9.4)
EMG0: 3 (IC11.41), 4 (C35.2 R52.2 TP22.1)
EMG1: 3 (IC11.55), 7 (C56.1 R93.2 TP29.1)
EXHAUST: 3 (IC11.26), 8 (C71.1 R75.2)
FWV: 3 (IC11.45), 8 (IC9.3)
HVMOS: 3 (IC11.28), 8 (C88.1 R142.2)
IAC_AD: 3 (IC11.29), 6 (C12.1 R9.2 TP5.1)
IAC_SHUNT: 1 (BG1.4 C8.2 R1.2 Z2.2), 6 (R2.1)
IGBT: 3 (IC11.17), 8 (C73.1 R79.2)
IV+: 5 (13 pins), 7 (R99.1 R100.1 R103.1)
LED1: 3 (IC11.33), 9 (R67.2 TP12.1)
LED2: 3 (IC11.34), 9 (R68.2 TP13.1)
LED3: 3 (IC11.10), 9 (R69.2 TP14.1)
LED4: 3 (IC11.7), 9 (R70.2 TP15.1)
OUTPIPE: 3 (IC11.25), 8 (C70.1 R73.2)
OUTROOM: 3 (IC11.27), 8 (C69.1 R71.2)
PFC_BRK: 1 (R151.1), 6 (IC6.7)
PFC_FO: 3 (IC11.8), 6 (C19.1 R17.2 TP6.1)
PFC_PWM: 1 (R41.1 TP8.1), 3 (IC11.6)
PTC: 3 (IC11.20), 8 (IC9.1)
PTC_O: 1 (D1.1 RY1.4), 8 (IC9.16)
PWM_UH0: 3 (IC11.35), 4 (IC8.15 TP16.1)
PWM_UH1: 3 (IC11.49), 5 (R87.1 TP23.1)
PWM_UL0: 3 (IC11.36), 4 (IC8.12 TP19.1)
PWM_UL1: 3 (IC11.50), 5 (R84.1 TP26.1)
PWM_VH0: 3 (IC11.37), 4 (IC8.14 TP17.1)
PWM_VH1: 3 (IC11.51), 5 (R88.1 TP24.1)
PWM_VL0: 3 (IC11.38), 4 (IC8.11 TP20.1)
PWM_VL1: 3 (IC11.52), 5 (R85.1 TP27.1)
PWM_WH0: 3 (IC11.39), 4 (IC8.13 TP18.1)
PWM_WH1: 3 (IC11.53), 5 (R89.1 TP25.1)
PWM_WL0: 3 (IC11.40), 4 (IC8.10 TP21.1)
PWM_WL1: 3 (IC11.54), 5 (R86.1 TP28.1)
RESET: 3 (C38.2 IC11.63 R81.1), 9 (IC15.4)
RXD0: 3 (IC11.32), 9 (R35.1)
RXD2: 3 (IC11.2), 9 (C30.1 R48.1)
TXD0: 3 (IC11.31), 9 (R36.1)
TXD2: 3 (IC11.3), 9 (R47.1)
VAC_AD: 3 (IC11.30), 6 (C28.1 R34.2 TP7.1)
VDC_AD: 3 (IC11.19), 7 (5 pins)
